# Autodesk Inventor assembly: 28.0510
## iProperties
Created: 2007-06
Part Number: 28.0510
Document SubType Name: Assembly
Designer: Andy Moles
Description: TIMING BELT PULLEY LR 6
Author: Andy Moles
